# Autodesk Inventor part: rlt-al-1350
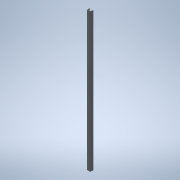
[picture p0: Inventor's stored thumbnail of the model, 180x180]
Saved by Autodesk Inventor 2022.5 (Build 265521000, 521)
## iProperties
Created: 2016-12
Part Number: rlt-al-1350
Material: 一般
Document SubType Name: Modeling
Designer: imaocorp
Density: 1 g/cm^3
Appearance: 既定
Author: imaocorp
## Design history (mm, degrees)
node "rlt-al-1350.x_t1"
node "rlt-al-1350"
node "Base1"
